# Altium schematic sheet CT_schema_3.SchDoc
size 312 x 238 mm
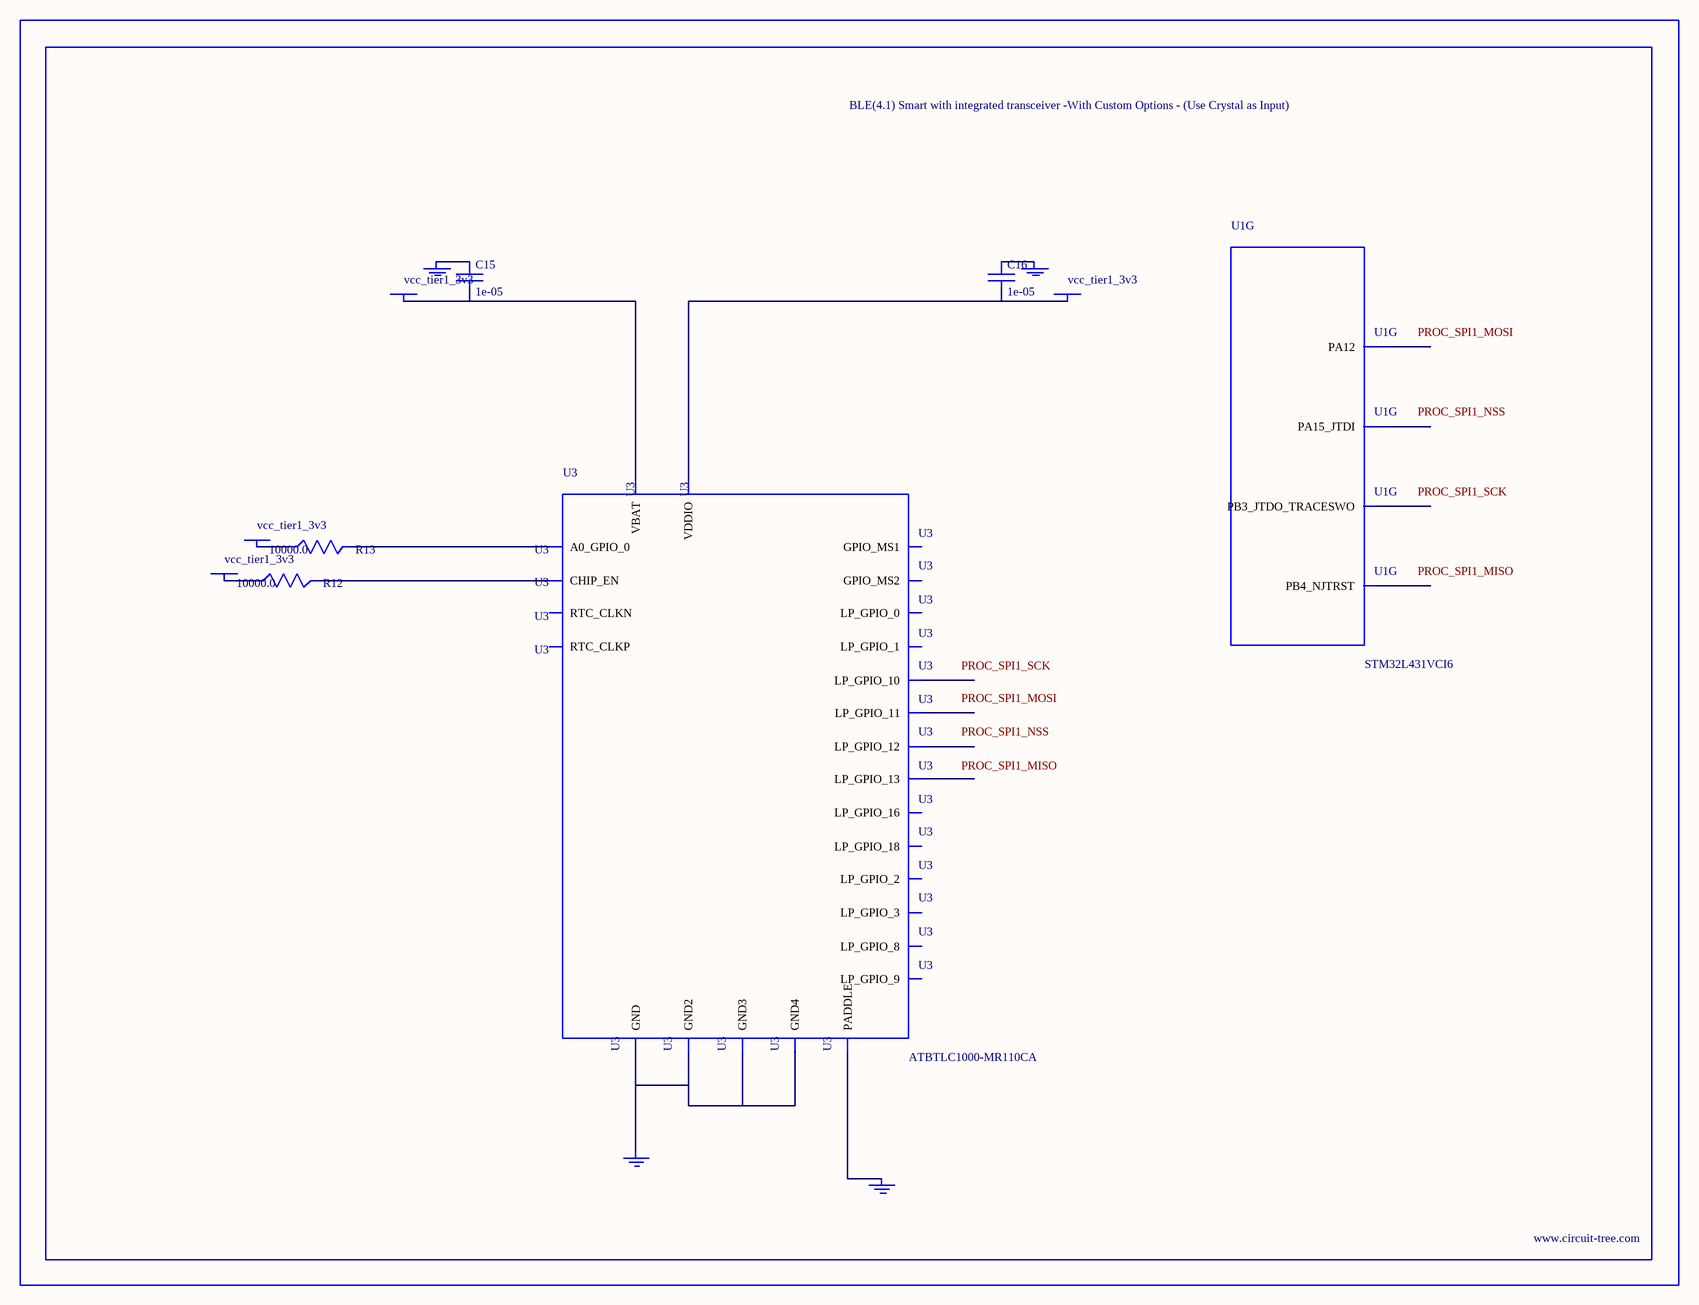
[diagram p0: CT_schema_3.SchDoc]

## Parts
BORDER2  (no value)
C15  1e-05  [C0805]
C16  1e-05  [C0805]
GND_INSTANCE_2_0  (no value)
GND_INSTANCE_2_1  (no value)
GND_INSTANCE_2_2  (no value)
GND_INSTANCE_2_3  (no value)
POWER_INSTANCE_2_0  vcc_tier1_3v3
POWER_INSTANCE_2_1  vcc_tier1_3v3
POWER_INSTANCE_2_2  vcc_tier1_3v3
POWER_INSTANCE_2_3  vcc_tier1_3v3
R12  10000.0  [R0603]
R13  10000.0  [R0603]
U1  STM32L431VCI6  [UFBGA100]  (part G of 9)
U3  ATBTLC1000-MR110CA  [ATBTLC1000-MR110CA]

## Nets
NetC15_1: C15.1 GND_INSTANCE_2_0.0(GND)
NetC15_2: C15.2 POWER_INSTANCE_2_0.0(PWR) U3.6(VBAT)
NetC16_1: C16.1 GND_INSTANCE_2_1.0(GND)
NetC16_2: C16.2 POWER_INSTANCE_2_3.0(PWR) U3.22(VDDIO)
NetGND_INSTANCE_2_2_0: GND_INSTANCE_2_2.0(GND) U3.25(PADDLE)
NetGND_INSTANCE_2_3_0: GND_INSTANCE_2_3.0(GND) U3.1(GND) U3.9(GND2) U3.13(GND3) U3.24(GND4)
NetPOWER_INSTANCE_2_1_0: POWER_INSTANCE_2_1.0(PWR) R12.1
NetPOWER_INSTANCE_2_2_0: POWER_INSTANCE_2_2.0(PWR) R13.1
NetR12_2: R12.2 U3.17(CHIP_EN)
NetR13_2: R13.2 U3.20(A0_GPIO_0)

Not connected (* = marked no-connect by the designer): U1 A7(PB4_NJTRST) A8(PB3_JTDO_TRACESWO) A9(PA15_JTDI) A12(PA12); U3 2(LP_GPIO_0) 3(LP_GPIO_1) 4(LP_GPIO_2) 5(LP_GPIO_3) 7(LP_GPIO_8) 8(LP_GPIO_9) 10(LP_GPIO_10) 11(LP_GPIO_11) 12(LP_GPIO_12) 14(LP_GPIO_13) 15(GPIO_MS1) 16(GPIO_MS2) 18(RTC_CLKP) 19(RTC_CLKN) 21(LP_GPIO_16) 23(LP_GPIO_18)

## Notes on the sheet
- Labels drawn without touching a wire or pin: PROC_SPI1_MISO, PROC_SPI1_MOSI, PROC_SPI1_NSS, PROC_SPI1_SCK

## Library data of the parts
BORDER2 = BORDER_PAGE2
C15 C16 = C0805C106K8RACTU
GND_INSTANCE_2_0-GND_INSTANCE_2_3 = GND
POWER_INSTANCE_2_0-POWER_INSTANCE_2_3 = PWR
R12 R13 = RC0603JR-0710KL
